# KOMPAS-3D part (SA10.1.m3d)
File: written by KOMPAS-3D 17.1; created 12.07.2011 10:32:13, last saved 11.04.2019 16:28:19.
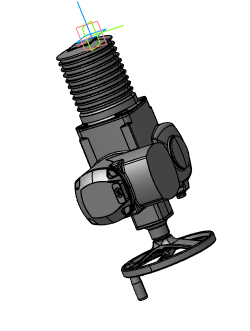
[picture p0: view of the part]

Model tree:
1. Плоскость XY
2. Плоскость ZX
3. Плоскость ZY
4. Ось X
5. Ось Y
6. Ось Z
7. Начало координат
8. Операция без истории:2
